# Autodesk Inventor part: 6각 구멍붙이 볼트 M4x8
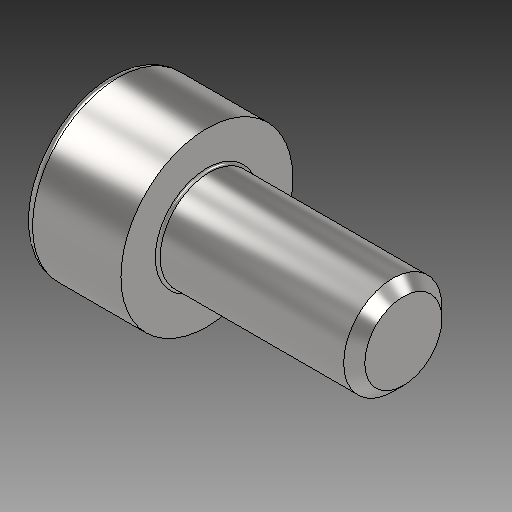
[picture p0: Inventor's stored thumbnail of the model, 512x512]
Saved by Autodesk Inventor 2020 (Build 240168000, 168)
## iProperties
Created: 2025-03
Part Number: 6각 구멍붙이 볼트 M4x8
Material: 강철, 연강
Description: 6각머리 태핑 나사
Document SubType Name: Modeling
Designer: CA01
Density: 7.85 g/cm^3
Appearance: 기본값
Author: jhkim
Sending System: Autodesk Inventor 2025
Preprocessor: ST-DEVELOPER v20
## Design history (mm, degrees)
feature "Solid1"
node "솔리드1"
